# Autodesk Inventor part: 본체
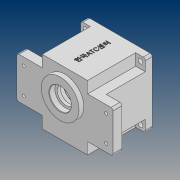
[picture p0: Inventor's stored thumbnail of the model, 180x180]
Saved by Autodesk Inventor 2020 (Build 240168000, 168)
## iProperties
Created: 2020-07
Part Number: 본체
Material: 일반
Document SubType Name: Modeling
Designer: PC312-
Density: 1 g/cm^3
Appearance: 기본값
Mass: 324.574 g
Surface Area: 793.93 cm^2
Volume: 324.574 cm^3
Author: PC312-
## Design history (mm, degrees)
sketch "스케치1"
  geometry: L1 (0, 0)-(0, 94); L2 (0, 94)-(-33, 94); L3 (-33, 94)-(-33, 77); L4 (-33, 77)-(-70, 77); L5 (-70, 77)-(-70, 17); L6 (-70, 17)-(-33, 17); L7 (-33, 17)-(-33, 0); L8 (-33, 0)-(0, 0); L9 (0, 94)-(33, 94); L10 (33, 94)-(33, 77); L11 (33, 77)-(70, 77); L12 (70, 77)-(70, 17); L13 (70, 17)-(33, 17); L14 (33, 17)-(33, 0); L15 (33, 0)-(0, 0); L16 (-84.809, 47)-(80.616, 47)
  constraints: 32 end point, 6 symmetric about line, 5 horizontal, 4 point on line, 3 vertical
  dimensions: "d0" = 94 distance of L1.start L1.end; "d1" = 140 distance between parallel lines of L12 L5; "d2" = 60 distance between parallel lines of L13 L11; "d3" = 47 distance between parallel lines of L15 L16; "d4" = 33 distance between parallel lines of L1 L3; "d5" = 30 distance between parallel lines of L16 L4
extrude "돌출1" new body sketch "스케치1" distance "d6" = 13; taper "d7" = 0 deg
node "작업 평면1"
sketch "스케치3"
  geometry: L1 (-47, 0)-(47, 0); L2 (47, 0)-(47, 94); L3 (47, 94)-(-47, 94); L4 (-47, 94)-(-47, 0); L5 (-47, 0)-(47, 94); L6 (47, 0)-(-47, 94); 3 further points
  constraints: 12 end point, 3 midpoint, 2 parallel, 1 coincident, 1 horizontal, 1 perpendicular
  dimensions: "d11" = 94 distance of L2.end L3.end; "d12" = 94 distance of L1.end L2.end
extrude "돌출2" join sketch "스케치3" distance "d13" = 10; taper "d14" = 0 deg
sketch "스케치4"
  geometry: L1 (-47, 0)-(-47, 94) reference; L2 (47, 94)-(47, 0) reference; L3 (-70, 77)-(-33, 77) reference; L4 (-33, 77)-(-33, 94) reference; L5 (-33, 94)-(33, 94) reference; L6 (33, 94)-(33, 77) reference; L7 (33, 77)-(70, 77) reference; L8 (70, 17)-(33, 17) reference; L9 (33, 17)-(33, 0) reference; L10 (-33, 17)-(-70, 17) reference; L11 (-33, 0)-(-33, 17) reference; L12 (33, 0)-(-33, 0) reference; 5 further points
extrude "돌출3" join sketch "스케치4" stored distance "d15" = 10; taper "d16" = 0 deg
sketch "스케치5"
  geometry: L1 (-33, 0)-(33, 0) reference; L2 (33, 17)-(70, 17) reference; C1 r 27.5 at (0, 58); 2 further points
  constraints: 1 centre point, 1 midpoint, 1 vertical alignment
  dimensions: "d17" = 55 diameter of C1; "d18" = 41 distance from line of C1.centre L2
extrude "돌출4" join sketch "스케치5" distance "d19" = 7; taper "d20" = 0 deg
sketch "스케치6"
  geometry: L1 (47, 0)-(-47, 0) reference; C1 r 43 at (0, 47); 2 further points
  constraints: 1 centre point, 1 midpoint, 1 vertical alignment
  dimensions: "d21" = 86 diameter of C1; "d22" = 47 distance of C1.centre point (0, 0)
extrude "돌출5" cut sketch "스케치6" distance "d23" = 9; taper "d24" = 0 deg
sketch "스케치7"
  geometry: C1 r 43 at (0, 0) reference; C2 r 40 at (0, 0); 1 further point
  constraints: 1 centre point, 1 coincident
  dimensions: "d25" = 80 diameter of C2
extrude "돌출6" cut sketch "스케치7" distance "d26" = 62; taper "d27" = 0 deg
sketch "스케치8"
  geometry: C1 r 43 at (0, 0) reference; A1 r 21 centre (0, 11) between (8.978, -7.984) and (-8.978, -7.984); A2 r 15 centre (0, -20) between (-8.978, -7.984) and (8.978, -7.984); 1 further point
  constraints: 4 point on circle, 2 centre point, 2 vertical alignment
  dimensions: "d28" = 11 distance of A1.centre C1.centre; "d29" = 42 diameter of A1; "d30" = 30 diameter of A2; "d31" = 20 distance of A2.centre C1.centre
extrude "돌출7" join sketch "스케치8" distance "d32" = 7; taper "d33" = 0 deg
sketch "스케치9"
  geometry: L1 (47, 30.341)-(47, -74.969); L2 (0, -57)-(0, 13) reference; L3 (58, 30.341)-(58, -74.969); L4 (85.5, 20)-(30.5, 20) reference; L5 (74, 20)-(74, 11.7); L6 (74, 11.7)-(70.5, 11.7); L7 (70.5, 11.7)-(70.5, 7); L8 (70.5, 7)-(75.5, 7); L9 (75.5, 7)-(75.5, -3); L10 (39.016, -3)-(79, -3) reference; L11 (74, 20)-(58, 20); L12 (75.5, -3)-(58, -3); 2 further points
  constraints: 18 end point, 4 point on line, 4 vertical, 2 horizontal, 1 midpoint, 1 parallel
  dimensions: "d34" = 47 distance between parallel lines of L1 L2; "d35" = 11 distance between parallel lines of L1 L3; "d36" = 32 diameter of L5 L3; "d37" = 25 diameter of L7 L3; "d38" = 35 diameter of L9 L3; "d39" = 8.3 distance between parallel lines of L4 L6; "d40" = 10 distance between parallel lines of L10 L8
revolve "회전1" sketch "스케치9" stored, may be unused: angle "d41" = 90 deg
sketch "스케치10"
  geometry: L1 (27, 23.438)-(27, -84.761); L2 (47, 29.056)-(47, -82.353); L3 (0, -57)-(0, 13) reference; L4 (27, 7)-(36.5, 7); L5 (36.5, 7)-(36.5, 4); L6 (36.5, 4)-(38, 4); L7 (38, 4)-(38, -3); L8 (38, -3)-(27, -3); L9 (12, -3)-(39.016, -3) reference; 1 further point
  constraints: 14 end point, 4 point on line, 4 vertical, 2 horizontal
  dimensions: "d42" = 47 distance between parallel lines of L2 L3; "d43" = 20 distance between parallel lines of L1 L2; "d44" = 3 distance between parallel lines of L6 L4; "d45" = 7 distance between parallel lines of L8 L6; "d46" = 19 diameter of L5 L1; "d47" = 22 diameter of L7 L1
revolve "회전2" sketch "스케치10" stored, may be unused: angle "d48" = 90 deg
sketch "스케치11"
  geometry: C1 r 43 at (0, 0) reference; A1 r 40 centre (0, 0) between (-39.279, 7.559) and (-39.279, -7.559) reference; A2 r 36 centre (0, 0) between (-36, 0) and (-35.772, 4.045); A3 r 4 centre (-36, 0) between (-36.19, -3.995) and (-36.19, 3.995); A4 r 3 centre (-36.333, 6.992) between (-39.279, 7.559) and (-35.772, 4.045); A5 r 3 centre (-36.333, -6.992) between (-35.772, -4.045) and (-39.279, -7.559); 1 further point
  constraints: 13 point on circle, 4 centre point, 4 tangent, 1 coincident, 1 horizontal alignment
  dimensions: "d49" = 72 diameter of A2; "d50" = 8 diameter of A3; "d51" = 6 diameter of A4; "d52" = 6 diameter of A5
extrude "돌출8" join sketch "스케치11" distance "d53" = 62; taper "d54" = 0 deg
sketch "스케치12"
  geometry: L1 (-70, 77)-(-33, 77) reference; 3 further points
  constraints: 1 vertical alignment
  dimensions: "d62" = 60 horizontal distance of point (-60, 66) point (0, 0); "d63" = 11 distance from line of point (-60, 66) L1; "d64" = 38 distance of point (-60, 28) point (-60, 66)
hole "구멍1" sketch "스케치12" at (-60, 66), (-60, 28) diameter "d55" = 4.5; stored, may be unused: countersink angle "d59" = 90 deg, drill point angle "d61" = 118 deg; dims "d56" = 6, "d57" = 10, "d58" = 5, "d60" = 8
sketch "스케치13"
  geometry: L1 (-47, 94)-(47, 94) reference; L2 (47, 0)-(-47, 0) reference; 3 further points
  constraints: 1 vertical alignment
  dimensions: "d72" = 40 horizontal distance of point (-40, 87) point (0, 0); "d73" = 7 distance from line of point (-40, 87) L1; "d74" = 7 distance from line of point (-40, 7) L2
hole "구멍2" sketch "스케치13" at (-40, 87), (-40, 7) diameter "d65" = 7; stored, may be unused: countersink angle "d69" = 90 deg, drill point angle "d71" = 118 deg; dims "d66" = 6, "d67" = 10, "d68" = 5, "d70" = 8
sketch "스케치14"
  geometry: L1 (47, -47)-(-47, -47) reference; C1 r 43 at (0, 0) reference; C2 r 27.5 at (0, 11) reference; 2 further points
  dimensions: "d82" = 47 distance from line of point (-36, 0) L1; "d83" = 36 horizontal distance of C2.centre point (-36, 0)
hole "구멍3" sketch "스케치14" at (-36, 0) diameter "d75" = 3.242; stored, may be unused: countersink angle "d79" = 90 deg, drill point angle "d81" = 118 deg; dims "d76" = 7, "d77" = 10, "d78" = 5, "d80" = 9
chamfer "모따기1" distance "d84" = 0.8; stored, may be unused: second distance "d85" = 2, angle "d86" = 30 deg
fillet "모깎기1" dims "d87" = 3
chamfer "모따기2" distance "d88" = 1; stored, may be unused: second distance "d89" = 2, angle "d90" = 30 deg
chamfer "모따기3" distance "d91" = 1; stored, may be unused: second distance "d92" = 2, angle "d93" = 30 deg
chamfer "모따기4" distance "d94" = 1; stored, may be unused: second distance "d95" = 2, angle "d96" = 30 deg
fillet "모깎기2" dims "d97" = 3
fillet "모깎기3" dims "d98" = 3
node "작업 평면2"
sketch "스케치15"
  geometry: L1 (77, 80)-(-11, 80) reference; 2 further points
  constraints: 1 vertical alignment, 1 other
  dimensions: "d100" = 40 distance from line of L1 point (33, 40)
feature "엠보싱1" sketch "스케치15" dims "d0" = 94, "d1" = 140, "d2" = 60, "d3" = 47, "d4" = 33, "d5" = 30, "d11" = 94, "d12" = 94, "d101" = 0.5, "d102" = 0
node "솔리드1"
mirror "미러1"
mirror "미러2"
mirror "미러3"
mirror "미러4"
feature "A9D066F2-1C7D-4E18-AEED-F7BC21143FA4" dims "d55" = 4.5, "d56" = 6, "d57" = 10, "d58" = 5, "d59" = 90 deg, "d60" = 8, "d61" = 118 deg
